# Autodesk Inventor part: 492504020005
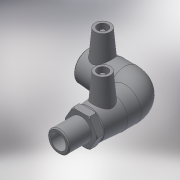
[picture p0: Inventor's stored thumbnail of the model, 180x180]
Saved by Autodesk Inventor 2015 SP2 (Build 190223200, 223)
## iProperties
Created: 2017-06
Part Number: 492504020005
Material: Generic
Description: PLASSON 90° ELBOW MALE TRANSITION 20-1/2"
Document SubType Name: Modeling
Designer: KIM
Mass: 65.9086 g
Surface Area: 234.541 cm^2
Volume: 65.9086 cm^3
Density: 1 g/cm^3
Appearance: Default
Author: KIM
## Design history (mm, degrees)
derived "492504.ipt"
feature "Solid1::492504.ipt"
tag "TaggingFeature1"
body "Solid1"
other parameters: "d2" = 32, "d4" = 22, "d5" = 28.8, "d8" = 168 deg, "d10" = 14, "d11" = 4.66667, "d29" = 38, "d30" = 15, "d31" = 36.3, "d34" = 5 deg, "d41" = 4, "d42" = 14, "d43" = 0, "d50" = 17, "d51" = 14, "d52" = 35, "d54" = 90 deg, "d58" = 35, "d59" = 0, "d61" = 90 deg, "d86" = 3, "d87" = 0, "d93" = 0.1, "d94" = 7.25, "d95" = 20.955, "d96" = 14.6685, "d97" = 14, "d98" = 29, "d99" = 32, "d100" = 26.1, "d102" = 1, "d106" = 0, "L_" = 95, "L_1" = 35, "D_" = 14, "A_" = 38, "d_2" = 12, "L_2" = 29, "D_1" = 32, "R_" = 20.955
